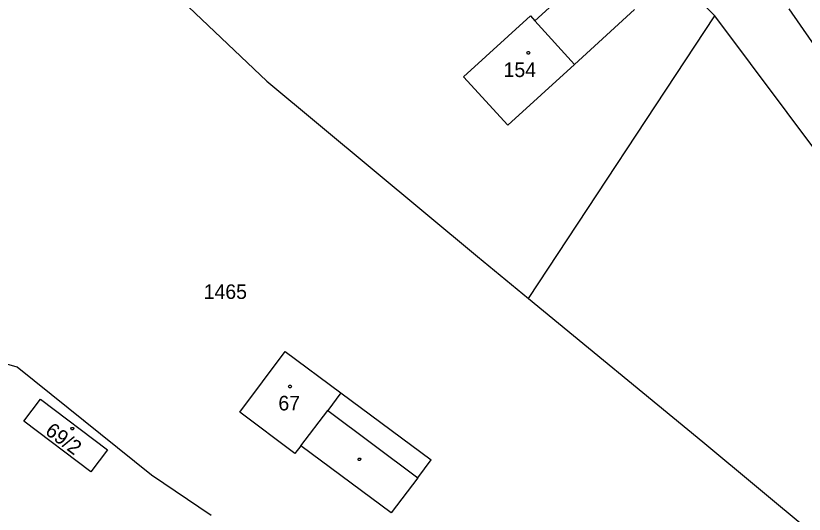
# Model space of a CAD drawing. Extents: x -852001 to -842497, y -1063614 to -1052182.
# Drawn here: x -849216.3 to -849124.2, y -1056153.1 to -1056094.9 of the extents above; entities that cross this region are included whole.
import ezdxf

# ---------------------------------------------------------------- set-up
doc = ezdxf.new("R2010")
doc.units = 0
for name, color, linetype in [('Default', 7, 'Continuous'), ('KN_HRANICE', 7, 'Continuous'), ('KN_KULTURY', 7, 'Continuous'), ('KN_PARCELY', 7, 'Continuous'), ('KN_SLUCKY', 7, 'Continuous')]:
    doc.layers.add(name, color=color, linetype=linetype)

# ---------------------------------------------------------------- blocks, each defined once
blk = doc.blocks.new('402')
at = {"layer": 'Default'}
blk.add_lwpolyline([(0.09, 0.15), (0.18, 0), (0.09, -0.15), (-0.09, -0.15), (-0.18, 0), (-0.09, 0.15), (0.09, 0.15)], dxfattribs=at)

msp = doc.modelspace()

# ---------------------------------------------------------------- linework, layer by layer
at = {"layer": 'KN_HRANICE'}
for p, q in [((-849144.79, -1056084.84), (-849134.65, -1056094.95)), ((-849144.79, -1056084.84), (-849134.65, -1056094.95)), ((-849155.67, -1056095.51), (-849148.74, -1056089.13)), ((-849155.67, -1056095.51), (-849148.74, -1056089.13)), ((-849196.89, -1056093.18), (-849186.98, -1056102.56)), ((-849196.89, -1056093.18), (-849186.98, -1056102.56)), ((-849144.01, -1056094.18), (-849151.02, -1056100.61)), ((-849144.01, -1056094.18), (-849151.02, -1056100.61)), ((-849125.98, -1056094.1), (-849108.8, -1056119.1)), ((-849125.98, -1056094.1), (-849108.8, -1056119.1)), ((-849164, -1056102.05), (-849156.19, -1056094.94)), ((-849164, -1056102.05), (-849156.19, -1056094.94)), ((-849156.39, -1056127.95), (-849134.65, -1056094.95)), ((-849156.39, -1056127.95), (-849134.65, -1056094.95)), ((-849156.19, -1056094.94), (-849155.67, -1056095.51)), ((-849156.19, -1056094.94), (-849155.67, -1056095.51)), ((-849113.79, -1056122.8), (-849134.65, -1056094.95)), ((-849113.79, -1056122.8), (-849134.65, -1056094.95)), ((-849151.02, -1056100.61), (-849158.83, -1056107.72)), ((-849151.02, -1056100.61), (-849158.83, -1056107.72)), ((-849186.98, -1056102.56), (-849162.35, -1056123.05)), ((-849186.98, -1056102.56), (-849162.35, -1056123.05)), ((-849158.83, -1056107.72), (-849164, -1056102.05)), ((-849158.83, -1056107.72), (-849164, -1056102.05)), ((-849162.35, -1056123.05), (-849156.39, -1056127.95)), ((-849162.35, -1056123.05), (-849156.39, -1056127.95)), ((-849156.39, -1056127.95), (-849136.05, -1056144.68)), ((-849156.39, -1056127.95), (-849136.05, -1056144.68)), ((-849216.14, -1056135.95), (-849229.16, -1056132.38)), ((-849216.14, -1056135.95), (-849229.16, -1056132.38)), ((-849190.13, -1056141.21), (-849184.82, -1056134.14)), ((-849190.13, -1056141.21), (-849184.82, -1056134.14)), ((-849184.82, -1056134.14), (-849178.32, -1056138.97)), ((-849184.82, -1056134.14), (-849178.32, -1056138.97)), ((-849200.44, -1056148.6), (-849216.14, -1056135.95)), ((-849200.44, -1056148.6), (-849216.14, -1056135.95)), ((-849178.32, -1056138.97), (-849167.78, -1056146.8)), ((-849178.32, -1056138.97), (-849167.78, -1056146.8)), ((-849183.69, -1056146.04), (-849190.13, -1056141.21)), ((-849183.69, -1056146.04), (-849190.13, -1056141.21)), ((-849136.05, -1056144.68), (-849108.72, -1056167.41)), ((-849136.05, -1056144.68), (-849108.72, -1056167.41)), ((-849183.02, -1056145.16), (-849183.69, -1056146.04)), ((-849183.02, -1056145.16), (-849183.69, -1056146.04)), ((-849172.44, -1056152.99), (-849183.02, -1056145.16)), ((-849172.44, -1056152.99), (-849183.02, -1056145.16)), ((-849169.35, -1056148.89), (-849167.78, -1056146.8)), ((-849169.35, -1056148.89), (-849167.78, -1056146.8)), ((-849193.48, -1056153.3), (-849200.44, -1056148.6)), ((-849193.48, -1056153.3), (-849200.44, -1056148.6)), ((-849169.35, -1056148.89), (-849172.44, -1056152.99)), ((-849169.35, -1056148.89), (-849172.44, -1056152.99))]:
    msp.add_line(p, q, dxfattribs=at)
at = {"layer": 'KN_SLUCKY'}
for p, q in [((-849155.67, -1056095.51), (-849151.02, -1056100.61)), ((-849155.67, -1056095.51), (-849151.02, -1056100.61)), ((-849178.32, -1056138.97), (-849179.84, -1056141.02)), ((-849178.32, -1056138.97), (-849179.84, -1056141.02)), ((-849215.38, -1056142.29), (-849213.42, -1056139.7)), ((-849215.38, -1056142.29), (-849213.42, -1056139.7)), ((-849213.42, -1056139.7), (-849205.59, -1056145.62)), ((-849213.42, -1056139.7), (-849205.59, -1056145.62)), ((-849183.02, -1056145.16), (-849179.84, -1056141.02)), ((-849183.02, -1056145.16), (-849179.84, -1056141.02)), ((-849179.84, -1056141.02), (-849169.35, -1056148.89)), ((-849179.84, -1056141.02), (-849169.35, -1056148.89)), ((-849207.55, -1056148.21), (-849215.38, -1056142.29)), ((-849207.55, -1056148.21), (-849215.38, -1056142.29)), ((-849205.59, -1056145.62), (-849207.55, -1056148.21)), ((-849205.59, -1056145.62), (-849207.55, -1056148.21))]:
    msp.add_line(p, q, dxfattribs=at)

# ---------------------------------------------------------------- block references
at = {"layer": 'KN_KULTURY'}
for p in [(-849156.42, -1056099.26), (-849156.42, -1056099.26), (-849184.27, -1056138.24), (-849184.27, -1056138.24), (-849209.7, -1056143.15), (-849209.7, -1056143.15), (-849176.16, -1056146.73), (-849176.16, -1056146.73)]:
    msp.add_blockref('402', p, dxfattribs=at)

# ---------------------------------------------------------------- texts
at = {"layer": 'KN_PARCELY'}
for s, p in [('154', (-849159.32, -1056102.08)), ('154', (-849159.32, -1056102.08)), ('1465', (-849194.36, -1056128)), ('1465', (-849194.36, -1056128)), ('67', (-849185.63, -1056141.02)), ('67', (-849185.63, -1056141.02))]:
    msp.add_text(s, height=1.7, dxfattribs=at).set_placement(p)
msp.add_text('69/2', height=1.7, rotation=323.492, dxfattribs=at).set_placement((-849213, -1056143.69))
msp.add_text('69/2', height=1.7, rotation=323.492, dxfattribs=at).set_placement((-849213, -1056143.69))

doc.saveas('drawing.dxf')
